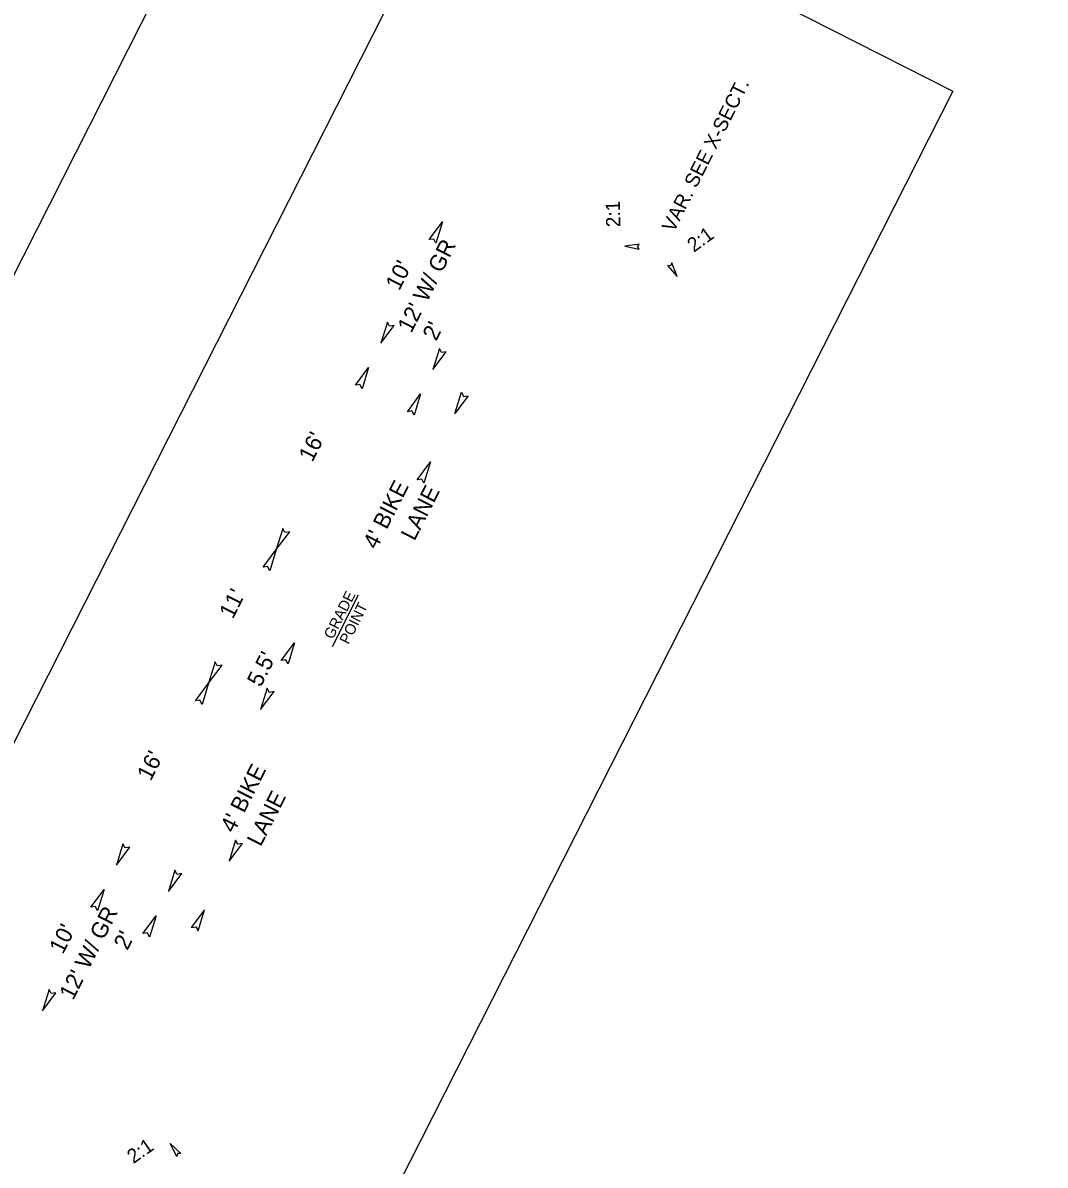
# Model space of a CAD drawing. Extents: x 1974386 to 1979988, y 776712 to 784860.
# Drawn here: x 1977629 to 1978080, y 778805 to 779309 of the extents above; entities that cross this region are included whole.
import ezdxf

# ---------------------------------------------------------------- set-up
doc = ezdxf.new("R2010")
doc.units = 0
for name, color, linetype in [('Default', 7, 'Continuous'), ('Old_Level_11', 7, 'Continuous'), ('Old_Level_3', 7, 'Continuous'), ('Old_Level_4', 7, 'Continuous')]:
    doc.layers.add(name, color=color, linetype=linetype)

msp = doc.modelspace()

# ---------------------------------------------------------------- linework, layer by layer
at = {"layer": 'Default'}
msp.add_lwpolyline([(1978009.96, 784859.92), (1974385.88, 777715.09), (1976364.02, 776711.71), (1979988.11, 783856.54)], close=True, dxfattribs=at)
at = {"layer": 'Old_Level_11'}
for points in [[(1977808.36, 779213.54), (1977814.2, 779221.37), (1977811.35, 779211.96), (1977810.37, 779213.83)], [(1977900.99, 779211.57), (1977894.65, 779210.6), (1977900.98, 779209.36), (1977900.2, 779210.5)], [(1977913.46, 779202.11), (1977917.74, 779197.35), (1977915.31, 779203.32), (1977914.79, 779202.04)], [(1977789.93, 779177.19), (1977787.06, 779167.86), (1977792.96, 779175.71), (1977790.88, 779175.39)], [(1977812.87, 779165.56), (1977809.99, 779156.23), (1977815.9, 779164.08), (1977813.81, 779163.76)], [(1977775.8, 779149.32), (1977781.63, 779157.15), (1977778.79, 779147.75), (1977777.81, 779149.62)], [(1977798.74, 779137.69), (1977804.57, 779145.52), (1977801.72, 779136.12), (1977800.75, 779137.99)], [(1977825.57, 779144.74), (1977819.74, 779136.91), (1977822.59, 779146.31), (1977823.56, 779144.44)], [(1977803.05, 779107.67), (1977808.88, 779115.5), (1977806.03, 779106.1), (1977805.06, 779107.97)], [(1977743.81, 779086.21), (1977740.93, 779076.88), (1977746.84, 779084.74), (1977744.75, 779084.41)], [(1977735.1, 779069.05), (1977740.93, 779076.88), (1977738.08, 779067.48), (1977737.11, 779069.35)], [(1977743.11, 779027.99), (1977748.94, 779035.82), (1977746.09, 779026.42), (1977745.12, 779028.29)], [(1977713.96, 779027.35), (1977711.09, 779018.02), (1977716.99, 779025.87), (1977714.91, 779025.55)], [(1977705.26, 779010.18), (1977711.09, 779018.02), (1977708.24, 779008.61), (1977707.27, 779010.48)], [(1977736.89, 779015.72), (1977734.02, 779006.39), (1977739.92, 779014.24), (1977737.84, 779013.92)], [(1977723, 778948.77), (1977720.12, 778939.43), (1977726.03, 778947.29), (1977723.94, 778946.97)], [(1977673.26, 778947.08), (1977670.39, 778937.74), (1977676.29, 778945.6), (1977674.21, 778945.28)], [(1977696.19, 778935.45), (1977693.32, 778926.12), (1977699.22, 778933.97), (1977697.14, 778933.65)], [(1977659.13, 778919.21), (1977664.96, 778927.04), (1977662.11, 778917.64), (1977661.14, 778919.51)], [(1977706.4, 778908.7), (1977709.27, 778918.03), (1977703.37, 778910.17), (1977705.45, 778910.49)], [(1977682.06, 778907.58), (1977687.89, 778915.41), (1977685.04, 778906.01), (1977684.07, 778907.88)], [(1977640.7, 778882.86), (1977637.83, 778873.53), (1977643.73, 778881.38), (1977641.65, 778881.06)], [(1977697.02, 778809.3), (1977694.06, 778814.98), (1977698.8, 778810.61), (1977697.42, 778810.58)]]:
    msp.add_lwpolyline(points, close=True, dxfattribs=at)
at = {"layer": 'Old_Level_3'}
msp.add_line((1977765.67, 779034.15), (1977777.23, 779056.95), dxfattribs=at)
at = {"layer": 'Old_Level_4'}
msp.add_lwpolyline([(1977508, 778760.75), (1977825.85, 779387.39), (1978039.36, 779279.09), (1977721.51, 778652.45)], close=True, dxfattribs=at)

# ---------------------------------------------------------------- texts
at = {"layer": 'Old_Level_11'}
for s, height, rotation, p in [('VAR. SEE X-SECT.', 6.276, 63.1133, (1977916.23, 779216.41)), ('2:1', 6.276, 91.3235, (1977892.69, 779219.11)), ('2:1', 6.276, 36.1126, (1977925.07, 779207.73)), ("12' W/ GR", 7.2, 63.1133, (1977800.45, 779172)), ("10'", 7.2, 63.1133, (1977795.17, 779190.71)), ("2'", 7.2, 63.1133, (1977811.48, 779168.51)), ("16'", 7.2, 63.1133, (1977756.83, 779115.09)), ("4' BIKE ", 7.2, 63.1133, (1977785.16, 779076.57)), ('LANE', 7.2, 63.1133, (1977801.88, 779080.35)), ("11'", 7.2, 63.1133, (1977721.77, 779045.94)), ('GRADE', 4.715, 63.1133, (1977765.85, 779037.01)), ('POINT', 4.715, 63.1133, (1977772.74, 779034.79)), ("5.5'", 7.2, 63.1133, (1977734.07, 779015.86)), ("16'", 7.2, 63.1133, (1977685.54, 778974.48)), ("4' BIKE ", 7.2, 63.1133, (1977722.26, 778951.51)), ('LANE', 7.2, 63.1133, (1977734.04, 778945.54)), ("12' W/ GR", 7.2, 63.1133, (1977651.29, 778877.81)), ("10'", 7.2, 63.1133, (1977646.82, 778898.12)), ("2'", 7.2, 63.1133, (1977675.25, 778899.84)), ('2:1', 6.276, 34.9031, (1977677.88, 778805.85))]:
    msp.add_text(s, height=height, rotation=rotation, dxfattribs=at).set_placement(p)

doc.saveas('drawing.dxf')
